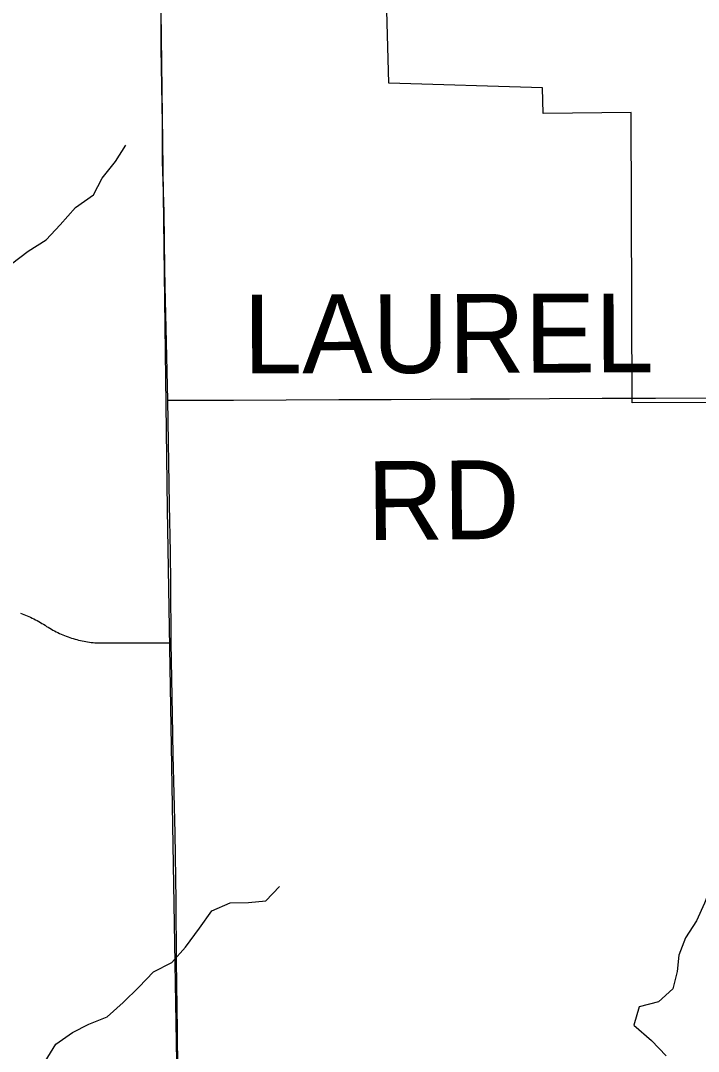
# Model space of a CAD drawing. Extents: x 0 to 34, y 0 to 22.
# Drawn here: x 4.6908 to 4.9349, y 18.5126 to 18.8839 of the extents above; entities that cross this region are included whole.
import ezdxf

# ---------------------------------------------------------------- set-up
doc = ezdxf.new("R2010")
doc.units = 0
for name, color, linetype in [('GM_X_Corporation', 7, 'Continuous'), ('GM_X_Minor_River', 7, 'Continuous'), ('GM_X_Rail_Line', 7, 'Continuous'), ('GM_X_Township_Road', 7, 'Continuous'), ('GM_X_Township_Road_Text', 7, 'Continuous')]:
    doc.layers.add(name, color=color, linetype=linetype)

msp = doc.modelspace()

# ---------------------------------------------------------------- linework, layer by layer
at = {"layer": 'GM_X_Corporation'}
msp.add_lwpolyline([(5.23824, 18.51969), (5.07403, 18.51973), (5.07403, 18.53536), (4.94603, 18.54009), (4.94969, 18.63913), (5.00182, 18.63916), (4.99954, 18.74659), (4.91104, 18.74623), (4.91072, 18.85089), (4.87904, 18.85042), (4.87879, 18.85978), (4.82345, 18.86141), (4.81894, 19.02246), (4.78728, 19.06894), (4.78736, 19.11456), (4.81907, 19.11531), (4.8192, 19.14384), (4.80056, 19.14349), (4.79982, 19.1925), (4.79903, 19.27751), (4.83707, 19.27827), (4.8349, 19.44686), (4.73296, 19.44721), (4.7308, 19.63688)], dxfattribs=at)
at = {"layer": 'GM_X_Minor_River'}
for points in [[(4.68746, 18.79628), (4.69351, 18.80084), (4.69995, 18.80502), (4.70505, 18.81034), (4.71054, 18.8166), (4.71697, 18.82117), (4.72018, 18.82724), (4.72491, 18.83313), (4.72869, 18.83902)], [(4.94121, 18.59453), (4.94011, 18.58483), (4.94025, 18.57876), (4.93964, 18.57248), (4.93714, 18.56597), (4.93426, 18.55964), (4.93024, 18.55348), (4.92792, 18.54735), (4.9273, 18.54146), (4.92574, 18.53516), (4.92056, 18.53049), (4.9136, 18.52862), (4.91167, 18.52212), (4.91804, 18.51658), (4.92327, 18.511)], [(4.69963, 18.50893), (4.70341, 18.5152), (4.70947, 18.51938), (4.71533, 18.52242), (4.72196, 18.52508), (4.72764, 18.53021), (4.73331, 18.53572), (4.73861, 18.54123), (4.74523, 18.54465), (4.75015, 18.55016), (4.75525, 18.557), (4.7596, 18.56327), (4.76623, 18.56612), (4.77285, 18.56632), (4.7791, 18.56689), (4.78402, 18.57202)]]:
    msp.add_lwpolyline(points, dxfattribs=at)
at = {"layer": 'GM_X_Rail_Line'}
msp.add_lwpolyline([(4.76791, 17.00293), (4.79375, 17.14663), (4.79991, 17.2068), (4.80568, 17.24767), (4.80796, 17.29563), (4.80745, 17.36765), (4.80531, 17.38086), (4.79833, 17.40059), (4.77663, 17.43675), (4.76364, 17.46488), (4.7557, 17.50103), (4.75403, 17.51651), (4.75612, 17.80268), (4.75391, 18.09859), (4.74923, 18.38092), (4.74367, 18.7078), (4.73815, 19.14265), (4.73332, 19.55441), (4.7315, 19.92628), (4.72821, 20.24009), (4.74767, 20.27759), (4.79462, 20.37419), (4.79387, 20.42708)], dxfattribs=at)
at = {"layer": 'GM_X_Township_Road'}
msp.add_line((4.91946, 18.74798), (4.98726, 18.74832), dxfattribs=at)
for points in [[(4.74738, 18.50575), (4.74728, 18.52001), (4.74688, 18.54538), (4.74681, 18.56696), (4.74642, 18.59125), (4.74602, 18.6054), (4.74565, 18.61939), (4.74544, 18.63403), (4.74501, 18.65982), (4.74485, 18.68113), (4.74471, 18.69244), (4.74441, 18.70948), (4.74378, 18.74727), (4.74326, 18.76801), (4.74287, 18.78823), (4.74273, 18.79464), (4.74244, 18.8149), (4.74192, 18.83334), (4.74187, 18.84685), (4.74144, 18.87401), (4.74134, 18.89044)], [(4.74378, 18.74727), (4.75626, 18.74717), (4.76746, 18.74722), (4.7864, 18.74731), (4.80542, 18.74741), (4.82421, 18.7475), (4.83847, 18.74758), (4.85278, 18.74765), (4.86692, 18.74772), (4.88126, 18.74779), (4.9002, 18.74789), (4.91946, 18.74798)], [(4.69069, 18.67052), (4.69131, 18.67029), (4.69193, 18.67006), (4.69255, 18.66982), (4.69316, 18.66956), (4.69377, 18.6693), (4.69437, 18.66902), (4.69497, 18.66874), (4.69557, 18.66845), (4.69615, 18.66814), (4.69674, 18.66783), (4.69732, 18.6675), (4.69789, 18.66717), (4.69845, 18.66682), (4.69901, 18.66647), (4.69956, 18.66611), (4.70012, 18.66574), (4.70068, 18.66539), (4.70125, 18.66505), (4.70182, 18.66471), (4.7024, 18.66439), (4.70298, 18.66408), (4.70357, 18.66377), (4.70416, 18.66348), (4.70476, 18.6632), (4.70537, 18.66293), (4.70598, 18.66266), (4.70659, 18.66241), (4.70721, 18.66217), (4.70783, 18.66194), (4.70846, 18.66173), (4.70909, 18.66152), (4.70972, 18.66132), (4.71036, 18.66114), (4.711, 18.66096), (4.71164, 18.6608), (4.71229, 18.66064), (4.71294, 18.6605), (4.71359, 18.66037), (4.71424, 18.66025), (4.7149, 18.66015), (4.71556, 18.66005), (4.71621, 18.65996), (4.71688, 18.65989), (4.71754, 18.65983), (4.7182, 18.65978), (4.71886, 18.65974), (4.74194, 18.65979), (4.74501, 18.65982)]]:
    msp.add_lwpolyline(points, dxfattribs=at)

# ---------------------------------------------------------------- texts
at = {"layer": 'GM_X_Township_Road_Text'}
for s, rotation, p in [('LAUREL', 0.1741, (4.77108, 18.75681)), ('RD', 0.4936, (4.8157, 18.69679))]:
    msp.add_text(s, height=0.028409, rotation=rotation, dxfattribs=at).set_placement(p)

doc.saveas('drawing.dxf')
